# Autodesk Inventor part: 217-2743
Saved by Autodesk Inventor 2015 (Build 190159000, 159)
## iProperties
Created: 2014-11
Part Number: 217-2743
Material: Generic
Document SubType Name: Modeling
Designer: User
Density: 1 g/cm^3
Appearance: Default
Author: User
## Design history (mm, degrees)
node "217-2743.ipt1"
node "Imported1"
node "Imported2"
node "Imported3"
node "Base1"
node "Base2"
node "Base3"
